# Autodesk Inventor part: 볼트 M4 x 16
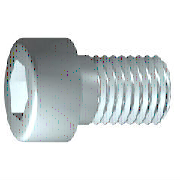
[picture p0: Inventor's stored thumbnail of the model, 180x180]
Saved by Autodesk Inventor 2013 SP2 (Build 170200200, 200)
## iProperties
Created: 2012-02
Part Number: 볼트 M4 x 16
Material: 스테인리스강
Description: 6각 소켓 머리 캡 나사
Document SubType Name: Modeling
Standard: ISO 4762
Designer: mduedu
Standard Revision: Fourth edition 2004-03-01
Standards Organization: ISO
Language: ko-KR
Size Designation: M4 x 16
Categories: <MemberInstance><Categories><Category DisplayName="조임쇠" InternalName="e4da775c-781d-43d5-af7c-5136215cf5a6" Mnemonic="FSTN"><Category DisplayName="볼트" InternalN
Density: 8.08 g/cm^3
Mass: 2.70334 g
Surface Area: 3.81118 cm^2
Volume: 0.334572 cm^3
IsCustomPart: 0
Author: mduedu
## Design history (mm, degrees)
sketch "스케치1"
  geometry: L1 (-1, 0)-(16, 0); L2 (16, 0)-(16, 2); L3 (16, 2)-(1.75, 2); L4 (1.75, 2)-(1.32, 2); L5 (1.32, 2)-(0, 2); L6 (0, 2)-(0, 3.5); L7 (0, 3.5)-(-4, 3.5); L8 (-4, 3.5)-(-4, 1.732); L9 (-4, 1.732)-(-2, 1.732); L10 (-2, 1.732)-(-1, 0); L11 (-8, 0)-(20, 0) reference; L12 (0, -0.7)-(0, 4.2) reference; L13 (1.75, 2)-(0, 2)
  constraints: 22 end point, 6 parallel, 2 collinear, 2 perpendicular, 1 horizontal, 1 point on line
  dimensions: "d1" = 14.25 distance from line of L3.end L2 (= GEL); "d2" = 0.42952 distance of L4.end L3.end (computed from GAL); "d3" = 4 distance between parallel lines of L8 L6 (= KOH); "d4" = 2 distance of L8.end L9.end (= INTI); "d5" = 60 deg angle of L10 L1; "d6" = 4 diameter of L3 L1 (= GD); "d7" = 4 diameter of L5 L1 (= BDM); "d8" = 3.4641 diameter of L9 L1 (= 1.1547 x SW); "d9" = 7 diameter of L7 L1 (= KOD); "d26" = 16 distance between parallel lines of L12 L2 (= NLG)
revolve "본체" sketch "스케치1" stored, may be unused: angle "d10" = 90 deg
sketch "스케치2"
  geometry: L1 (0, -4.9)-(0, 4.9) reference; L2 (-4.9, 0)-(4.9, 0) reference; L3 (1.732, 0)-(0.866, -1.5); L4 (0.866, -1.5)-(-0.866, -1.5); L5 (-0.866, -1.5)-(-1.732, 0); L6 (-1.732, 0)-(-0.866, 1.5); L7 (-0.866, 1.5)-(0.866, 1.5); L8 (0.866, 1.5)-(1.732, 0); 2 further points
  constraints: 12 end point, 1 coincident, 1 horizontal alignment, 1 point on line, 12 other
extrude "슬롯" join sketch "스케치2" stored distance "d11" = 10; taper "d12" = 0 deg
workplane "Work Plane1"
fillet "Fillet2" dims "d30" = 0.1 (= R)
body "Solid1"
fillet "모깎기1" dims "d17" = 0.4 (= RR)
feature "스레드" dims "d13" = 14.25 (= GEL), "d14" = 0
chamfer "모따기1" distance "d15" = 0.42941 (= -0.5 x SPD + 0.5 x GD); stored, may be unused: second distance "d16" = 0.42941 (= GUL), angle "d27" = 45 deg
other parameters: "GD" = 4 [user parameter; used in 2 equation terms], "NLG" = 16 [user parameter; used in 1 equation term], "GEL" = 14.25 [user parameter; used in 2 equation terms], "KOD" = 7 [user parameter; used in 1 equation term], "KOH" = 4 [user parameter; used in 1 equation term], "INTI" = 2 [user parameter; used in 1 equation term], "GAL" = 0.42941 (= 0.61345 x PTC) [user parameter; used in 1 equation term], "GUL" = 0.42941 (= 0.61345 x PTC) [user parameter; used in 1 equation term], "BDM" = 4 (= NND) [user parameter; used in 1 equation term], "SW" = 3 [user parameter; used in 2 equation terms], "RR" = 0.4 [user parameter; used in 1 equation term], "SPD" = 3.14117 (= NND - 1.2269 x PTC) [user parameter; used in 1 equation term], "d19" = 0, "d28" = 0, "d29" = 0, "R" = 0.1 [user parameter; used in 1 equation term], "TOA" = 30 deg [user parameter], "GD1" = 3.14117 (= THREADDIA - 1.2269 x PTC) [user parameter], "THREADDIA" = 4 [user parameter; used in 1 equation term], "FAWI" = 45 deg [user parameter], "TPU" = 14.28571 (computed from PTC) [user parameter], "PTC" = 0.7 [user parameter; used in 5 equation terms], "NND" = 4 [user parameter; used in 2 equation terms], "E0" = 3.465 (= 1.155 x SW) [user parameter]
